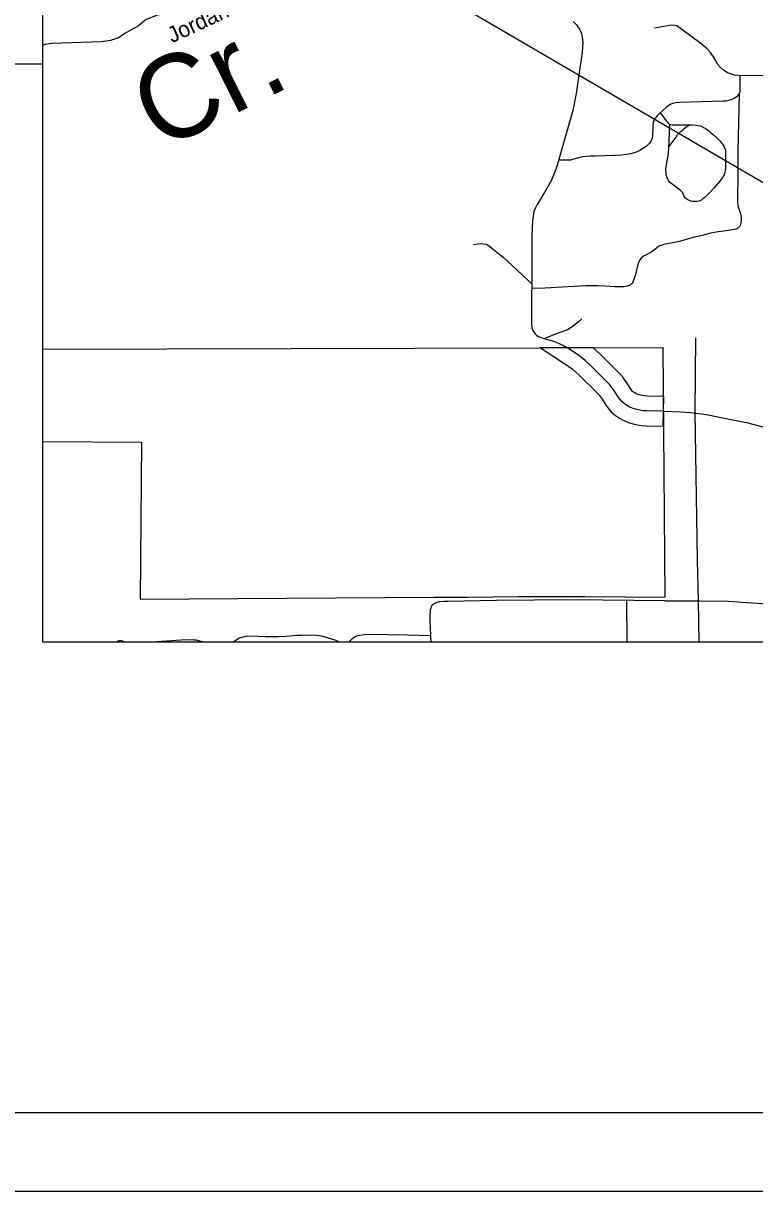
# Model space of a CAD drawing. Extents: x 19118 to 454486, y 1325406 to 1693506.
# Drawn here: x 24877 to 25247, y 1325406 to 1325997 of the extents above; entities that cross this region are included whole.
import ezdxf

# ---------------------------------------------------------------- set-up
doc = ezdxf.new("R2010")
doc.units = 0
for name, color, linetype in [('Default', 7, 'Continuous'), ('S_CURB', 7, 'Continuous'), ('S_EDGE_PAVEMENT', 7, 'Continuous'), ('S_PAVEMENT_CROWN', 7, 'Continuous'), ('S_SHOULDER', 7, 'Continuous')]:
    doc.layers.add(name, color=color, linetype=linetype)

msp = doc.modelspace()

# ---------------------------------------------------------------- linework, layer by layer
at = {"layer": 'Default'}
for p, q in [((25200.92, 1325793.29), (25201.22, 1325808.29)), ((24887.1, 1325785.55), (24937.17, 1325785.08)), ((24937.17, 1325785.08), (24936.44, 1325705.75))]:
    msp.add_line(p, q, dxfattribs=at)
for points in [[(24967.48, 1326006.01), (24944.74, 1326001.02), (24939.53, 1325998.93), (24935.62, 1325995.79), (24929.62, 1325992.38), (24925.45, 1325989.77), (24921.53, 1325988.46), (24916.84, 1325987.67), (24891.8, 1325986.89), (24888.41, 1325986.36), (24887.1, 1325985.81)], [(25155.39, 1325997.93), (25157.05, 1325996.27), (25158.59, 1325994.13), (25159.6, 1325991.99), (25160.02, 1325989.97), (25160.31, 1325987.48), (25159.9, 1325982.25), (25158.48, 1325972.15), (25156.94, 1325961.57), (25155.28, 1325952.9), (25147.1, 1325924.62), (25146.33, 1325922.36), (25145.44, 1325920.23), (25144.5, 1325917.73), (25142.36, 1325913.81), (25139.76, 1325909.53), (25137.15, 1325905.37), (25136.32, 1325903.71), (25135.61, 1325901.81), (25135.14, 1325899.55), (25134.9, 1325897.06), (25134.54, 1325889.57), (25134.48, 1325878.64), (25134.31, 1325845.37), (25134.54, 1325843.23), (25134.81, 1325842.22), (25135.25, 1325841.33), (25136.2, 1325840.02), (25137.03, 1325839.19), (25137.89, 1325838.66), (25139.31, 1325838.06), (25141.15, 1325837.47), (25144.35, 1325836.52), (25146.42, 1325835.87), (25148.61, 1325834.91), (25150.57, 1325833.98), (25152.51, 1325832.88)], [(25281.2, 1325970.23), (25239.13, 1325970.66), (25237.1, 1325970.87), (25235.38, 1325971.31), (25233.33, 1325972.19), (25231.54, 1325973.39), (25229.92, 1325974.75), (25228.63, 1325976.3), (25227.53, 1325978.05), (25226.37, 1325980.06), (25225.59, 1325981.29), (25224.75, 1325982.4), (25223.18, 1325984.17), (25220.15, 1325986.65), (25209.79, 1325994.38), (25207.78, 1325995.76), (25206.04, 1325996.07), (25204.2, 1325996.03), (25196.5, 1325994.65)], [(25239.68, 1325970.65), (25239.68, 1325962.38), (25239.07, 1325961.01), (25237.96, 1325959.9), (25236.78, 1325959.11), (25235.22, 1325958.37), (25233.99, 1325957.96), (25232.76, 1325957.72), (25231.12, 1325957.63), (25209.23, 1325956.98), (25207.26, 1325956.81), (25206.5, 1325956.69), (25205.7, 1325956.48), (25204.9, 1325956.15), (25204.14, 1325955.74), (25203.38, 1325955.21), (25202.75, 1325954.76), (25200.53, 1325952.78), (25199.06, 1325951.38), (25198.05, 1325950.4), (25197.36, 1325949.62), (25196.74, 1325948.88), (25196.21, 1325947.97), (25195.88, 1325946.86), (25195.72, 1325945.59), (25195.68, 1325943.33), (25195.59, 1325941.52), (25195.47, 1325940.2), (25195.31, 1325938.93), (25195.1, 1325938.06), (25194.65, 1325937.28), (25194.08, 1325936.46), (25193.42, 1325935.72), (25192.58, 1325934.94), (25191.58, 1325934.2), (25190.51, 1325933.5), (25189.16, 1325932.72), (25187.72, 1325932.06), (25186.2, 1325931.48), (25184.4, 1325930.99), (25182.43, 1325930.62), (25179.88, 1325930.37), (25176.73, 1325930.25), (25166.63, 1325929.92), (25164.27, 1325929.84), (25161.79, 1325929.67), (25160.05, 1325929.47), (25158.28, 1325929.06), (25155.15, 1325928.11), (25154.02, 1325927.87), (25152.91, 1325927.77), (25150.16, 1325927.77), (25148.01, 1325927.77)], [(25239.39, 1325961.32), (25238.65, 1325932.58), (25238.69, 1325921.95)], [(25199.42, 1325951.73), (25202.57, 1325947.64), (25202.94, 1325947.17), (25203.37, 1325946.7), (25203.86, 1325946.29), (25204.3, 1325946.04), (25204.79, 1325945.83), (25205.44, 1325945.7), (25206.14, 1325945.65), (25206.86, 1325945.63), (25215.61, 1325945.7), (25217.59, 1325945.55), (25218.7, 1325945.38), (25219.74, 1325945.14), (25220.83, 1325944.72), (25221.4, 1325944.44), (25222.1, 1325944.07), (25222.88, 1325943.53), (25223.62, 1325942.96), (25224.89, 1325941.89), (25226.45, 1325940.61), (25228.04, 1325939.09), (25229.03, 1325938.1), (25229.6, 1325937.53), (25230.09, 1325936.99), (25230.91, 1325935.97), (25231.65, 1325934.86), (25232.14, 1325933.79), (25232.39, 1325932.92), (25232.51, 1325931.2), (25232.47, 1325928.32), (25232.39, 1325923.91), (25232.27, 1325922.36), (25231.98, 1325921), (25231.73, 1325920.38), (25231.45, 1325919.89), (25231.08, 1325919.31), (25230.46, 1325918.41), (25229.56, 1325917.18), (25228.66, 1325916.06), (25226.34, 1325913.43), (25224.85, 1325911.83), (25223.37, 1325910.35), (25221.66, 1325908.74), (25221.07, 1325908.21), (25220.54, 1325907.8), (25219.76, 1325907.35), (25219.15, 1325907.1), (25218.04, 1325906.9), (25216.89, 1325906.85), (25215.74, 1325906.94), (25214.97, 1325907.1), (25214.19, 1325907.35), (25213.45, 1325907.68), (25212.87, 1325908.05), (25212.38, 1325908.5), (25211.64, 1325909.49), (25211.19, 1325910.47), (25210.82, 1325911.25), (25210.58, 1325911.62), (25210.29, 1325911.91), (25209.55, 1325912.57), (25205.54, 1325915.61), (25204.35, 1325916.52), (25203.49, 1325917.71), (25203.08, 1325918.61), (25202.75, 1325919.48), (25202.54, 1325920.38), (25202.41, 1325921.42), (25202.34, 1325923.14), (25202.46, 1325924.7), (25203.57, 1325931.28), (25203.65, 1325932.18), (25203.77, 1325933.38), (25204.39, 1325946)], [(25214.31, 1325945.69), (25210.93, 1325943.13), (25210.47, 1325942.77), (25210.04, 1325942.41), (25209.5, 1325941.93), (25208.99, 1325941.43), (25208.4, 1325940.82), (25207.92, 1325940.25), (25207.45, 1325939.62), (25206.61, 1325938.55), (25203.84, 1325934.72)], [(25238.69, 1325921.95), (25238.62, 1325906.97), (25238.78, 1325904.86), (25239.1, 1325903.65), (25239.41, 1325902.65), (25239.83, 1325901.27), (25240.2, 1325899.9), (25240.36, 1325898.69), (25240.34, 1325897.35), (25240.2, 1325896.06), (25240.1, 1325895.48), (25239.89, 1325894.84), (25239.68, 1325894.37), (25239.26, 1325893.89), (25238.68, 1325893.42), (25237.89, 1325893), (25236.05, 1325892.55), (25232.78, 1325892.03), (25228.81, 1325891.51), (25225.02, 1325890.82), (25220.02, 1325889.61), (25216.06, 1325888.74), (25212.61, 1325887.71), (25209.68, 1325886.84), (25208.32, 1325886.5), (25206.75, 1325886.15), (25202.96, 1325885.46), (25201.26, 1325885.16), (25200.39, 1325884.9), (25199.58, 1325884.6), (25198.65, 1325884.08), (25197.64, 1325883.34), (25195.37, 1325881.66), (25194.36, 1325880.92), (25192.34, 1325879.93), (25191.41, 1325879.41), (25190.83, 1325879.02), (25190.01, 1325878.33), (25189.32, 1325877.51), (25188.63, 1325876.34), (25188.2, 1325875.04), (25186.73, 1325869.3), (25186.28, 1325868), (25186, 1325867.05), (25185.57, 1325866.06), (25185.05, 1325865.36), (25184.39, 1325864.8), (25183.76, 1325864.41), (25182.92, 1325864.11), (25182.08, 1325863.9), (25181.11, 1325863.77), (25179.86, 1325863.68), (25178.33, 1325863.68), (25176.46, 1325863.77), (25171.59, 1325864.03), (25167.97, 1325864.2), (25161.76, 1325864.2), (25141.08, 1325862.99), (25134.4, 1325862.82)], [(25104.96, 1325885.15), (25108.55, 1325885.63), (25111.56, 1325885.3), (25113.18, 1325884.34), (25115.22, 1325882.58), (25118.49, 1325879.94), (25120.01, 1325878.78), (25134.41, 1325865.37)], [(25159.82, 1325847.62), (25158.08, 1325846.05), (25155.43, 1325843.89), (25152.57, 1325841.92), (25148.7, 1325840.63), (25140.86, 1325837.55)], [(25217.31, 1325837.91), (25217.04, 1325800.24)], [(24887.1, 1325832.2), (25200.84, 1325833), (25201.73, 1325706.73)], [(25165.56, 1325832.91), (25138.93, 1325832.84), (25151.21, 1325824.76), (25153.32, 1325823.4), (25154.92, 1325822.18)], [(25201.07, 1325800.79), (25192.71, 1325800.95), (25190.86, 1325801.07), (25189.07, 1325801.31), (25187.69, 1325801.61), (25185.78, 1325802.21), (25184.17, 1325802.87), (25182.67, 1325803.65), (25181.36, 1325804.55), (25179.98, 1325805.75), (25179.03, 1325806.89), (25178.19, 1325808.09), (25176.34, 1325811.02), (25175.17, 1325812.65), (25174.54, 1325813.48), (25173.89, 1325814.2), (25171.32, 1325816.9), (25165.7, 1325822.41), (25163.84, 1325824.27), (25161.45, 1325826.49), (25159.6, 1325828.05), (25157.63, 1325829.55), (25155.3, 1325831.05), (25152.51, 1325832.88)], [(25201.22, 1325808.29), (25193.03, 1325808.45), (25191.6, 1325808.54), (25190.36, 1325808.71), (25189.62, 1325808.87), (25188.32, 1325809.28), (25187.32, 1325809.68), (25186.54, 1325810.1), (25185.95, 1325810.49), (25185.35, 1325811.02), (25184.98, 1325811.46), (25184.44, 1325812.24), (25182.56, 1325815.21), (25181.21, 1325817.1), (25180.31, 1325818.29), (25179.37, 1325819.32), (25176.66, 1325822.16), (25170.98, 1325827.74), (25169.05, 1325829.67), (25165.56, 1325832.91)], [(25154.92, 1325822.18), (25154.92, 1325822.19), (25156.49, 1325820.87), (25158.64, 1325818.87), (25160.41, 1325817.09), (25165.97, 1325811.64), (25168.41, 1325809.08), (25168.78, 1325808.67), (25169.13, 1325808.21), (25170.11, 1325806.84), (25171.94, 1325803.94), (25173.07, 1325802.32), (25174.61, 1325800.48), (25176.76, 1325798.61), (25178.81, 1325797.21), (25181.01, 1325796.06), (25183.24, 1325795.15), (25185.77, 1325794.36), (25187.77, 1325793.92), (25190.12, 1325793.61), (25192.4, 1325793.46), (25200.92, 1325793.29)], [(25201.07, 1325800.79), (25205.61, 1325800.67), (25209.67, 1325800.52), (25214.67, 1325800.16), (25217.42, 1325799.87), (25220.25, 1325799.43), (25223.73, 1325798.92), (25227.72, 1325798.2), (25240.44, 1325795.62), (25243.09, 1325795.01)], [(25217.04, 1325800.24), (25218.21, 1325725.48), (25218.7, 1325704.87)], [(25243.09, 1325795.01), (25246.27, 1325794.27), (25251.93, 1325792.75), (25255.77, 1325791.65), (25258.52, 1325790.71), (25261.42, 1325789.69), (25263.74, 1325788.75), (25264.83, 1325788.24), (25266.28, 1325787.37), (25267.58, 1325786.42), (25268.89, 1325785.33), (25270.77, 1325783.34)], [(24936.44, 1325705.75), (25084.95, 1325706.68), (25101.93, 1325706.68), (25115.17, 1325706.92), (25127.69, 1325707.04), (25161.41, 1325707.04), (25201.73, 1325706.73)], [(25201.74, 1325704.87), (25154.52, 1325705.29), (25116.74, 1325704.99), (25092.11, 1325704.57), (25090.07, 1325704.51), (25088.02, 1325704.33), (25087.12, 1325704.14), (25086.11, 1325703.83), (25085.56, 1325703.61), (25084.96, 1325703.3), (25084.43, 1325702.89), (25084.02, 1325702.44), (25083.65, 1325701.86), (25083.37, 1325701.12), (25083.16, 1325700.22), (25083.04, 1325699.11), (25083.02, 1325697.94), (25083.02, 1325694.74), (25083.31, 1325687.39), (25083.43, 1325684.11)], [(25182.48, 1325705.04), (25182.65, 1325684.11)], [(25201.74, 1325704.87), (25219.46, 1325704.87), (25233.95, 1325704.61), (25243.09, 1325704.07)], [(25218.7, 1325704.87), (25218.96, 1325684.11)], [(25243.09, 1325704.07), (25256.92, 1325703.25), (25274.8, 1325702.36), (25281.89, 1325702.02), (25290.27, 1325701.93), (25297.87, 1325701.85), (25318.08, 1325702.31)], [(25036.85, 1325684.11), (25035.57, 1325684.85), (25028.39, 1325687), (25025.57, 1325687.4), (25020.77, 1325687.53), (25017.97, 1325687.34), (25015.78, 1325687.26), (25012.39, 1325686.94), (25010.19, 1325686.76), (25006.49, 1325686.63), (25003.19, 1325686.61), (24999.59, 1325686.69), (24996.19, 1325686.77), (24990.27, 1325687.06), (24986.61, 1325685.93), (24985.34, 1325685.08), (24983.79, 1325684.11)], [(25042.33, 1325684.11), (25042.87, 1325684.85), (25043.77, 1325685.75), (25044.75, 1325686.49), (25045.57, 1325686.9), (25046.55, 1325687.31), (25047.62, 1325687.56), (25049.66, 1325687.8), (25052.57, 1325687.93), (25071.72, 1325687.6), (25083.31, 1325687.4)], [(24928.38, 1325684.11), (24927.17, 1325684.66), (24926.02, 1325684.72), (24925.41, 1325684.48), (24924.85, 1325684.25), (24924.71, 1325684.11)], [(24967.94, 1325684.11), (24966.55, 1325684.52), (24964.74, 1325684.95), (24963.73, 1325685.02), (24959.63, 1325685.17), (24944.97, 1325684.11)]]:
    msp.add_lwpolyline(points, dxfattribs=at)
at = {"layer": 'S_CURB'}
msp.add_line((24757.86, 1325976.56), (24887.1, 1325976.56), dxfattribs=at)
msp.add_lwpolyline([(26142.72, 1326309.74), (24887.1, 1326309.74), (24887.1, 1325684.11), (26142.72, 1325684.11)], close=True, dxfattribs=at)
at = {"layer": 'S_EDGE_PAVEMENT'}
msp.add_lwpolyline([(23759.74, 1327539.29), (27093.14, 1327539.29), (27093.14, 1325405.92), (23759.74, 1325405.92)], close=True, dxfattribs=at)
at = {"layer": 'S_PAVEMENT_CROWN'}
msp.add_lwpolyline([(25402.73, 1325828.09), (24751.06, 1326208.5)], dxfattribs=at)
at = {"layer": 'S_SHOULDER'}
msp.add_line((27045.61, 1325445.75), (23883.81, 1325445.75), dxfattribs=at)

# ---------------------------------------------------------------- texts
at = {"layer": 'Default'}
for s, height, rotation, p in [('Jordan', 8, 24.91033, (24952.51, 1325986.93)), ('Cr.', 42.24, 26.58115, (24946.4, 1325932.1))]:
    msp.add_text(s, height=height, rotation=rotation, dxfattribs=at).set_placement(p)

doc.saveas('drawing.dxf')
